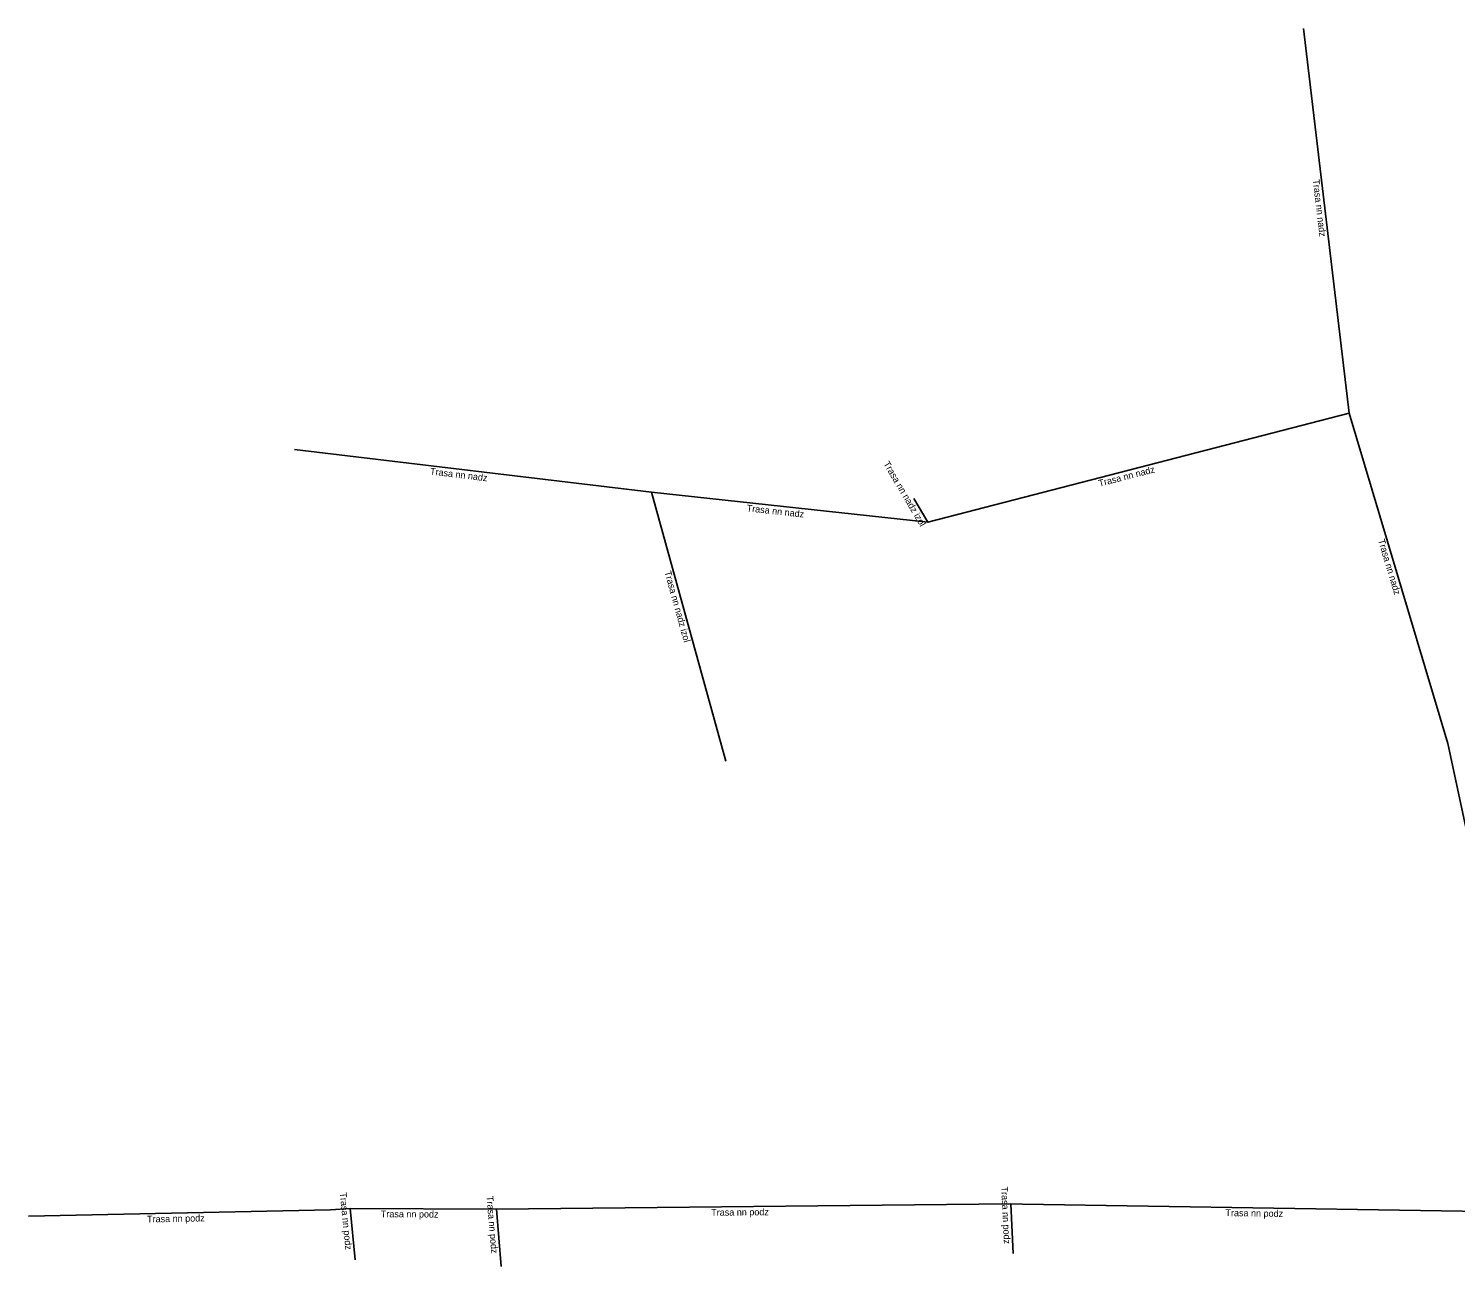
# Model space of a CAD drawing. Extents: x -778104 to -777779, y -1025034 to -1024901.
# Drawn here: x -778104.3 to -777998.5, y -1025005.7 to -1024913.9 of the extents above; entities that cross this region are included whole.
import ezdxf

# ---------------------------------------------------------------- set-up
doc = ezdxf.new("R2010")
doc.units = 0
doc.layers.add('Popiskový text - Ostatní atributy Trasy', color=7, linetype='Continuous')
doc.layers.add('Spojnice NN', color=7, linetype='Continuous')

msp = doc.modelspace()

# ---------------------------------------------------------------- linework, layer by layer
at = {"layer": 'Spojnice NN'}
for points in [[(-778006.4, -1024942.44), (-778009.78, -1024913.93)], [(-778037.63, -1024950.53), (-778006.4, -1024942.44)], [(-778006.4, -1024942.44), (-777999.08, -1024966.94)], [(-778084.56, -1024945.14), (-778058.11, -1024948.3)], [(-778058.11, -1024948.3), (-778037.63, -1024950.53)], [(-778058.11, -1024948.3), (-778052.61, -1024968.24)], [(-778037.63, -1024950.53), (-778038.67, -1024948.77)], [(-777999.08, -1024966.94), (-777994.32, -1024989.16)], [(-778104.28, -1025001.97), (-778081.89, -1025001.5), (-778080.44, -1025001.39)], [(-778069.6, -1025001.45), (-778080.44, -1025001.39)], [(-778080.44, -1025001.39), (-778080.06, -1025005.2)], [(-778069.6, -1025001.45), (-778031.48, -1025001.06)], [(-778069.6, -1025001.45), (-778069.24, -1025005.7)], [(-778031.48, -1025001.06), (-778031.3, -1025004.73)], [(-777993.35, -1025001.66), (-778030.6, -1025001.07), (-778031.48, -1025001.06)]]:
    msp.add_lwpolyline(points, dxfattribs=at)

# ---------------------------------------------------------------- texts
at = {"layer": 'Popiskový text - Ostatní atributy Trasy'}
for s, rotation, p in [('Trasa nn nadz', 276.7698, (-778009.1, -1024925.14)), ('Trasa nn nadz izol', 300.4342, (-778040.94, -1024946.19)), ('Trasa nn nadz', 353.1687, (-778074.54, -1024946.99)), ('Trasa nn nadz', 14.519, (-778024.9, -1024947.9)), ('Trasa nn nadz', 353.795, (-778051.07, -1024949.72)), ('Trasa nn nadz', 286.6194, (-778004.26, -1024951.86)), ('Trasa nn nadz izol', 285.4289, (-778057.15, -1024954.21)), ('Trasa nn podz', 272.7844, (-778032.19, -1024999.78)), ('Trasa nn podz', 275.6227, (-778081.21, -1025000.23)), ('Trasa nn podz', 274.8563, (-778070.34, -1025000.49)), ('Trasa nn podz', 1.2044, (-778095.49, -1025002.44)), ('Trasa nn podz', 359.7145, (-778078.17, -1025002.05)), ('Trasa nn podz', 0.574, (-778053.68, -1025001.94)), ('Trasa nn podz', 359.0957, (-778015.57, -1025001.96))]:
    msp.add_text(s, height=0.5, rotation=rotation, dxfattribs=at).set_placement(p)

doc.saveas('drawing.dxf')
